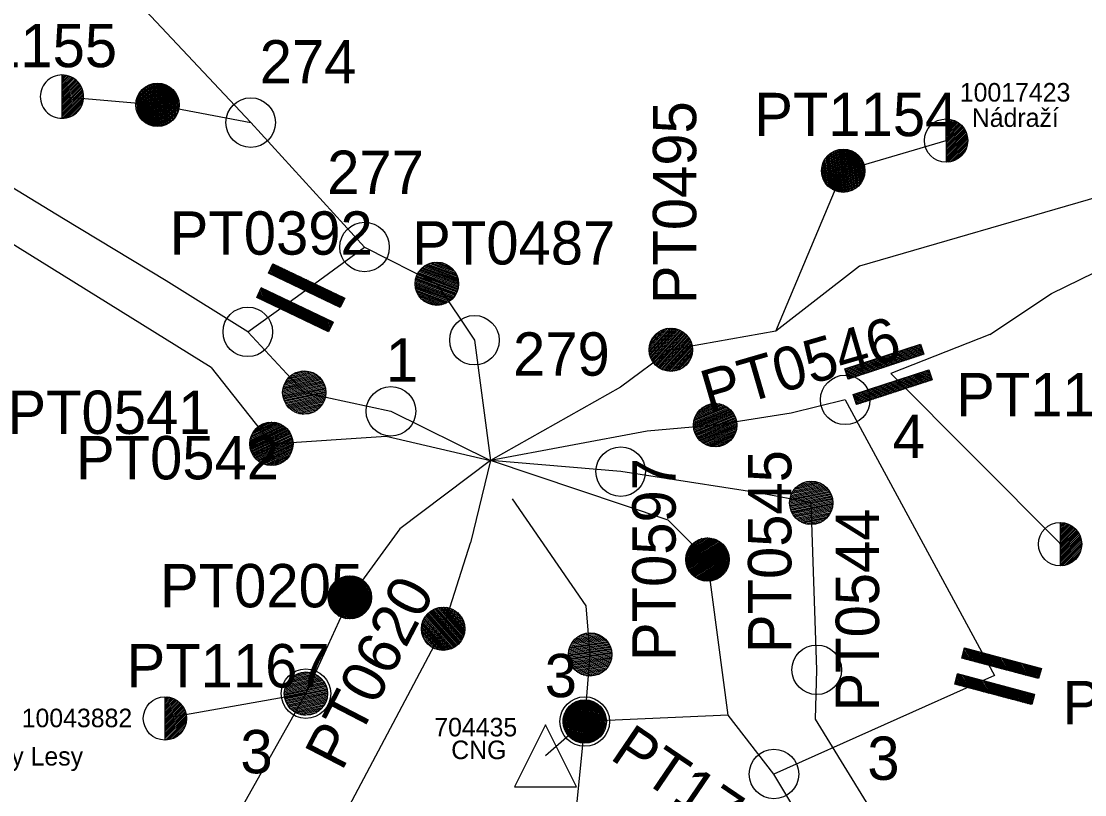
# Model space of a CAD drawing. Extents: x -788977 to -785292, y -1155262 to -1151579.
# Drawn here: x -787986 to -787127, y -1153978 to -1153353 of the extents above; entities that cross this region are included whole.
import ezdxf

# ---------------------------------------------------------------- set-up
doc = ezdxf.new("R2010")
doc.units = 0
for name, color, linetype in [('Default', 7, 'Continuous'), ('Vrstva 1', 7, 'Continuous'), ('Vrstva 2', 7, 'Continuous'), ('Vrstva 3', 7, 'Continuous'), ('Vrstva 44', 7, 'Continuous'), ('Vrstva 5', 7, 'Continuous')]:
    doc.layers.add(name, color=color, linetype=linetype)

# ---------------------------------------------------------------- blocks, each defined once
blk = doc.blocks.new('PS110')
at = {"layer": 'Default'}
for p, q in [((-15.14, 21.77), (-7.64, 29.27)), ((-15.14, 23.18), (-9.06, 29.27)), ((-15.14, 24.6), (-10.47, 29.27)), ((-15.14, 26.01), (-11.89, 29.27)), ((-15.14, 27.42), (-13.3, 29.27)), ((-15.14, 28.84), (-14.72, 29.27)), ((-15.14, 20.35), (-6.58, 28.92)), ((-15.14, 18.94), (-6.58, 27.5)), ((-15.14, 17.53), (-6.58, 26.09)), ((-6.58, -34.96), (-6.58, 29.27)), ((6.59, 22.11), (13.74, 29.27)), ((6.59, 20.7), (15.15, 29.26)), ((6.59, 23.53), (12.32, 29.26)), ((6.59, 24.94), (10.91, 29.26)), ((6.59, 26.36), (9.5, 29.26)), ((6.59, 27.77), (8.08, 29.26)), ((6.59, 29.18), (6.67, 29.26)), ((6.59, 19.29), (15.15, 27.85)), ((6.59, 17.87), (15.15, 26.44)), ((-15.14, 16.11), (-6.58, 24.68)), ((-15.14, 14.7), (-6.58, 23.26)), ((-15.14, 13.28), (-6.58, 21.85)), ((-15.14, 11.87), (-6.58, 20.43)), ((-15.14, 10.45), (-6.58, 19.02)), ((-15.14, 9.04), (-6.58, 17.61)), ((6.59, 16.46), (15.15, 25.02)), ((6.59, 15.04), (15.15, 23.61)), ((6.59, 13.63), (15.15, 22.19)), ((6.59, 12.21), (15.15, 20.78)), ((6.59, 10.8), (15.15, 19.37)), ((6.59, 9.39), (15.15, 17.95)), ((-15.14, 7.63), (-6.58, 16.19)), ((-15.14, 6.21), (-6.58, 14.78)), ((-15.14, 4.8), (-6.58, 13.36)), ((-15.14, 3.38), (-6.58, 11.95)), ((-15.14, 1.97), (-6.58, 10.54)), ((-15.14, 0.56), (-6.58, 9.12)), ((6.59, 7.97), (15.15, 16.54)), ((6.59, 6.56), (15.15, 15.12)), ((6.59, 5.14), (15.15, 13.71)), ((6.59, 3.73), (15.15, 12.29)), ((6.59, 2.32), (15.15, 10.88)), ((6.59, 0.9), (15.15, 9.47)), ((-15.14, -0.86), (-6.58, 7.71)), ((-15.14, -2.27), (-6.58, 6.29)), ((-15.14, -3.69), (-6.58, 4.88)), ((-15.14, -5.1), (-6.57, 3.46)), ((-15.14, -6.51), (-6.57, 2.05)), ((-15.14, -7.93), (-6.57, 0.64)), ((6.59, -0.51), (15.15, 8.05)), ((6.59, -1.93), (15.15, 6.64)), ((6.59, -3.34), (15.15, 5.22)), ((6.59, -4.75), (15.15, 3.81)), ((6.59, -6.17), (15.15, 2.4)), ((6.59, -7.58), (15.15, 0.98)), ((-15.14, -9.34), (-6.57, -0.78)), ((-15.14, -10.76), (-6.57, -2.19)), ((-15.14, -12.17), (-6.57, -3.61)), ((-15.14, -13.59), (-6.57, -5.02)), ((-15.14, -15), (-6.57, -6.43)), ((-15.14, -16.41), (-6.57, -7.85)), ((6.59, -9), (15.15, -0.43)), ((6.59, -10.41), (15.15, -1.85)), ((6.59, -11.83), (15.15, -3.26)), ((6.59, -13.24), (15.15, -4.67)), ((6.59, -14.65), (15.15, -6.09)), ((6.59, -16.07), (15.15, -7.5)), ((-15.14, -17.83), (-6.57, -9.26)), ((-15.14, -19.24), (-6.57, -10.68)), ((-15.14, -20.66), (-6.57, -12.09)), ((-15.14, -22.07), (-6.57, -13.5)), ((-15.14, -23.48), (-6.57, -14.92)), ((-15.14, -24.9), (-6.57, -16.33)), ((6.59, -17.48), (15.15, -8.92)), ((6.59, -18.9), (15.15, -10.33)), ((6.59, -20.31), (15.15, -11.74)), ((6.59, -21.72), (15.16, -13.16)), ((6.59, -23.14), (15.16, -14.57)), ((6.59, -24.55), (15.16, -15.99)), ((-15.14, -26.31), (-6.57, -17.75)), ((-15.14, -27.73), (-6.57, -19.16)), ((-15.14, -29.14), (-6.57, -20.58)), ((-15.14, -30.56), (-6.57, -21.99)), ((-15.14, -31.97), (-6.57, -23.4)), ((-15.14, -33.38), (-6.57, -24.82)), ((6.59, -25.97), (15.16, -17.4)), ((6.59, -27.38), (15.16, -18.82)), ((6.59, -28.79), (15.16, -20.23)), ((6.59, -30.21), (15.16, -21.64)), ((6.59, -31.62), (15.16, -23.06)), ((6.59, -33.04), (15.16, -24.47)), ((-15.14, -34.8), (-6.57, -26.23)), ((-13.89, -34.96), (-6.57, -27.65)), ((-12.47, -34.96), (-6.57, -29.06)), ((-11.06, -34.96), (-6.57, -30.47)), ((-9.64, -34.96), (-6.57, -31.89)), ((-8.23, -34.96), (-6.57, -33.3)), ((6.59, -34.45), (15.16, -25.89)), ((7.5, -34.96), (15.16, -27.3)), ((8.91, -34.96), (15.16, -28.71)), ((10.32, -34.96), (15.16, -30.13)), ((11.74, -34.96), (15.16, -31.54)), ((13.15, -34.96), (15.16, -32.96)), ((-6.82, -34.96), (-6.57, -34.72)), ((14.57, -34.96), (15.16, -34.37))]:
    blk.add_line(p, q, dxfattribs=at)
for points in [[(-6.58, 29.27), (-6.57, -34.96), (-15.14, -34.96), (-15.14, 29.27)], [(15.15, 29.27), (15.16, -34.96), (6.59, -34.96), (6.59, 29.26)]]:
    blk.add_lwpolyline(points, close=True, dxfattribs=at)
blk = doc.blocks.new('PS140')
at = {"layer": 'Default'}
for p, q in [((-17.49, -0.01), (0.01, 17.49)), ((-17.43, -1.37), (1.37, 17.43)), ((-17.42, 1.47), (-1.47, 17.42)), ((-17.29, -2.63), (2.63, 17.29)), ((-17.21, 3.1), (-3.1, 17.21)), ((-17.06, -3.82), (3.82, 17.06)), ((-16.77, -4.95), (4.95, 16.77)), ((-16.77, 4.95), (-4.95, 16.77)), ((-16.42, -6.01), (6.01, 16.42)), ((-16.02, -7.02), (7.02, 16.02)), ((-15.93, 7.2), (-7.2, 15.93)), ((-15.56, -7.98), (7.98, 15.56)), ((-15.06, -8.89), (8.89, 15.06)), ((-14.51, -9.76), (9.76, 14.51)), ((-13.92, -10.58), (10.58, 13.92)), ((-13.75, 10.8), (-10.8, 13.75)), ((-13.29, -11.36), (11.36, 13.29)), ((-12.62, -12.11), (12.11, 12.62)), ((-11.91, -12.81), (12.81, 11.91)), ((-11.15, -13.47), (13.47, 11.15)), ((-10.36, -14.09), (14.09, 10.36)), ((-9.52, -14.67), (14.67, 9.52)), ((-8.64, -15.2), (15.2, 8.64)), ((-7.72, -15.69), (15.69, 7.72)), ((-6.74, -16.13), (16.13, 6.74)), ((-5.72, -16.52), (16.52, 5.72)), ((-4.64, -16.86), (16.86, 4.64)), ((-3.5, -17.13), (17.13, 3.5)), ((-2.29, -17.34), (17.34, 2.29)), ((-1, -17.46), (17.46, 1)), ((0.39, -17.48), (17.48, -0.39)), ((1.91, -17.38), (17.38, -1.91)), ((3.59, -17.11), (17.11, -3.59)), ((5.53, -16.59), (16.59, -5.53)), ((7.96, -15.57), (15.57, -7.96))]:
    blk.add_line(p, q, dxfattribs=at)
blk.add_circle((0, 0), 17.49, dxfattribs=at)
blk = doc.blocks.new('PS150')
at = {"layer": 'Default'}
for p, q in [((-15.07, 22.36), (-7.37, 30.07)), ((-15.07, 23.78), (-8.78, 30.07)), ((-15.07, 25.19), (-10.2, 30.07)), ((-15.07, 26.6), (-11.61, 30.07)), ((-15.07, 28.02), (-13.03, 30.07)), ((-15.07, 29.43), (-14.44, 30.07)), ((-15.07, 20.95), (-6.51, 29.51)), ((-15.07, 19.53), (-6.51, 28.1)), ((-15.07, 18.12), (-6.51, 26.69)), ((6.66, 22.61), (14.12, 30.07)), ((6.66, 24.02), (12.7, 30.06)), ((6.66, 25.43), (11.29, 30.06)), ((6.66, 26.85), (9.87, 30.06)), ((6.66, 28.26), (8.46, 30.06)), ((6.66, 29.68), (7.04, 30.06)), ((6.66, 21.19), (15.22, 29.76)), ((6.66, 19.78), (15.22, 28.34)), ((6.66, 18.36), (15.22, 26.93)), ((-15.07, 16.71), (-6.51, 25.27)), ((-15.07, 15.29), (-6.51, 23.86)), ((-15.07, 13.88), (-6.51, 22.44)), ((-15.07, 12.46), (-6.51, 21.03)), ((-15.07, 11.05), (-6.51, 19.61)), ((-15.07, 9.64), (-6.51, 18.2)), ((6.66, 16.95), (15.22, 25.51)), ((6.66, 15.54), (15.22, 24.1)), ((6.66, 14.12), (15.22, 22.69)), ((6.66, 12.71), (15.22, 21.27)), ((6.66, 11.29), (15.22, 19.86)), ((6.66, 9.88), (15.22, 18.44)), ((-15.07, 8.22), (-6.51, 16.79)), ((-15.07, 6.81), (-6.51, 15.37)), ((-15.07, 5.39), (-6.51, 13.96)), ((-15.07, 3.98), (-6.5, 12.54)), ((-15.07, 2.56), (-6.5, 11.13)), ((-15.07, 1.15), (-6.5, 9.72)), ((6.66, 8.46), (15.22, 17.03)), ((6.66, 7.05), (15.22, 15.62)), ((6.66, 5.64), (15.22, 14.2)), ((6.66, 4.22), (15.22, 12.79)), ((6.66, 2.81), (15.22, 11.37)), ((6.66, 1.39), (15.22, 9.96)), ((-15.07, -0.26), (-6.5, 8.3)), ((-15.07, -1.68), (-6.5, 6.89)), ((-15.07, -3.09), (-6.5, 5.47)), ((-15.07, -4.51), (-6.5, 4.06)), ((-15.07, -5.92), (-6.5, 2.65)), ((-15.07, -7.33), (-6.5, 1.23)), ((6.66, -0.02), (15.22, 8.55)), ((6.66, -1.43), (15.22, 7.13)), ((6.66, -2.85), (15.22, 5.72)), ((6.66, -4.26), (15.22, 4.3)), ((6.66, -5.68), (15.22, 2.89)), ((6.66, -7.09), (15.22, 1.47)), ((6.66, -8.5), (15.22, 0.06)), ((-15.07, -8.75), (-6.5, -0.18)), ((-15.07, -10.16), (-6.5, -1.6)), ((-15.07, -11.58), (-6.5, -3.01)), ((-15.07, -12.99), (-6.5, -4.43)), ((-15.07, -14.4), (-6.5, -5.84)), ((-15.07, -15.82), (-6.5, -7.25)), ((6.66, -9.92), (15.22, -1.35)), ((6.66, -11.33), (15.22, -2.77)), ((6.66, -12.75), (15.22, -4.18)), ((6.66, -14.16), (15.23, -5.6)), ((6.66, -15.58), (15.23, -7.01)), ((6.66, -16.99), (15.23, -8.42)), ((-15.07, -17.23), (-6.5, -8.67)), ((-15.07, -18.65), (-6.5, -10.08)), ((-15.07, -20.06), (-6.5, -11.5)), ((-15.07, -21.48), (-6.5, -12.91)), ((-15.07, -22.89), (-6.5, -14.32)), ((-15.07, -24.3), (-6.5, -15.74)), ((-15.07, -25.72), (-6.5, -17.15)), ((6.66, -18.4), (15.23, -9.84)), ((6.66, -19.82), (15.23, -11.25)), ((6.66, -21.23), (15.23, -12.67)), ((6.66, -22.65), (15.23, -14.08)), ((6.66, -24.06), (15.23, -15.49)), ((6.66, -25.47), (15.23, -16.91)), ((-15.07, -27.13), (-6.5, -18.57)), ((-15.07, -28.55), (-6.5, -19.98)), ((-15.07, -29.96), (-6.5, -21.39)), ((-15.07, -31.37), (-6.5, -22.81)), ((-15.07, -32.79), (-6.5, -24.22)), ((-15.02, -34.16), (-6.5, -25.64)), ((6.66, -26.89), (15.23, -18.32)), ((6.66, -28.3), (15.23, -19.74)), ((6.66, -29.72), (15.23, -21.15)), ((6.66, -31.13), (15.23, -22.57)), ((6.66, -32.54), (15.23, -23.98)), ((6.66, -33.96), (15.23, -25.39)), ((-13.61, -34.16), (-6.5, -27.05)), ((-12.2, -34.16), (-6.5, -28.47)), ((-10.78, -34.16), (-6.5, -29.88)), ((-9.37, -34.16), (-6.5, -31.29)), ((-7.95, -34.16), (-6.5, -32.71)), ((-6.54, -34.16), (-6.5, -34.12)), ((7.87, -34.16), (15.23, -26.81)), ((9.29, -34.16), (15.23, -28.22)), ((10.7, -34.16), (15.23, -29.64)), ((12.12, -34.16), (15.23, -31.05)), ((13.53, -34.16), (15.23, -32.46)), ((14.95, -34.16), (15.23, -33.88))]:
    blk.add_line(p, q, dxfattribs=at)
for points in [[(-6.51, 30.07), (-6.5, -34.16), (-15.07, -34.16), (-15.07, 30.07)], [(15.22, 30.07), (15.23, -34.16), (6.66, -34.16), (6.66, 30.06)]]:
    blk.add_lwpolyline(points, close=True, dxfattribs=at)
blk = doc.blocks.new('PS610')
at = {"layer": 'Default'}
for p, q in [((0, 16.16), (1.27, 17.43)), ((0, 14.75), (2.54, 17.29)), ((0, 13.33), (3.75, 17.09)), ((0, 11.92), (4.86, 16.79)), ((0, 10.51), (5.93, 16.44)), ((0, 9.09), (6.95, 16.05)), ((0, 7.68), (7.9, 15.58)), ((0, 6.26), (8.83, 15.1)), ((0, 4.85), (9.69, 14.54)), ((0, 3.44), (10.52, 13.96)), ((0, 2.02), (11.3, 13.33)), ((0, 0.61), (12.05, 12.66)), ((0, -0.81), (12.76, 11.95)), ((0, -2.22), (13.42, 11.2)), ((0, -3.64), (14.05, 10.41)), ((0, -5.05), (14.62, 9.57)), ((0, -6.46), (15.17, 8.71)), ((0, -7.88), (15.65, 7.77)), ((0, -9.29), (16.1, 6.81)), ((0, -10.71), (16.49, 5.79)), ((0, -12.12), (16.83, 4.71)), ((0, -13.53), (17.12, 3.59)), ((0, -14.95), (17.32, 2.37)), ((0, -16.36), (17.44, 1.08)), ((0.29, -17.49), (17.48, -0.29)), ((1.78, -17.41), (17.4, -1.79)), ((3.46, -17.15), (17.14, -3.46)), ((5.36, -16.66), (16.65, -5.37)), ((7.78, -15.65), (15.64, -7.79))]:
    blk.add_line(p, q, dxfattribs=at)
blk.add_lwpolyline([(0, 17.5), (0, -17.5)], dxfattribs=at)
blk.add_circle((0, 0), 17.5, dxfattribs=at)
blk = doc.blocks.new('PS800')
at = {"layer": 'Vrstva 2'}
blk.add_circle((0, -0.01), 20, dxfattribs=at)
blk = doc.blocks.new('PS680')
at = {"layer": 'Vrstva 44'}
for points in [[(0, 25), (-25, -25)], [(25, -25), (0, 25)], [(-25, -25), (25, -25)]]:
    blk.add_lwpolyline(points, dxfattribs=at)
blk = doc.blocks.new('PS611')
at = {"layer": 'Default'}
for p, q in [((0, 16.16), (1.27, 17.43)), ((0, 14.75), (2.54, 17.29)), ((0, 13.33), (3.75, 17.09)), ((0, 11.92), (4.86, 16.79)), ((0, 10.51), (5.93, 16.44)), ((0, 9.09), (6.95, 16.05)), ((0, 7.68), (7.9, 15.58)), ((0, 6.26), (8.83, 15.1)), ((0, 4.85), (9.69, 14.54)), ((0, 3.44), (10.52, 13.96)), ((0, 2.02), (11.3, 13.33)), ((0, 0.61), (12.05, 12.66)), ((0, -0.81), (12.76, 11.95)), ((0, -2.22), (13.42, 11.2)), ((0, -3.64), (14.05, 10.41)), ((0, -5.05), (14.62, 9.57)), ((0, -6.46), (15.17, 8.71)), ((0, -7.88), (15.65, 7.77)), ((0, -9.29), (16.1, 6.81)), ((0, -10.71), (16.49, 5.79)), ((0, -12.12), (16.83, 4.71)), ((0, -13.53), (17.12, 3.59)), ((0, -14.95), (17.32, 2.37)), ((0, -16.36), (17.44, 1.08)), ((0.29, -17.49), (17.48, -0.29)), ((1.78, -17.41), (17.4, -1.79)), ((3.46, -17.15), (17.14, -3.46)), ((5.36, -16.66), (16.65, -5.37)), ((7.78, -15.65), (15.64, -7.79))]:
    blk.add_line(p, q, dxfattribs=at)
for points in [[(17.5, 0), (17.4, 1.83), (17.12, 3.64), (16.64, 5.4), (15.98, 7.11), (15.15, 8.75), (14.15, 10.28), (13, 11.71), (11.71, 13), (10.28, 14.15), (8.75, 15.15), (7.11, 15.98), (5.4, 16.64), (3.64, 17.12), (1.83, 17.4), (0, 17.5), (-1.83, 17.4), (-3.64, 17.12), (-5.41, 16.64), (-7.12, 15.98), (-8.75, 15.15), (-10.29, 14.15), (-11.71, 13), (-13.01, 11.71), (-14.16, 10.28), (-15.16, 8.75), (-15.99, 7.11), (-16.65, 5.4), (-17.12, 3.64), (-17.41, 1.83), (-17.5, 0), (-17.41, -1.83), (-17.12, -3.64), (-16.65, -5.41), (-15.99, -7.12), (-15.16, -8.75), (-14.16, -10.29), (-13.01, -11.71), (-11.71, -13.01), (-10.29, -14.16), (-8.75, -15.16), (-7.12, -15.99), (-5.41, -16.65), (-3.64, -17.12), (-1.83, -17.41), (0, -17.5), (1.83, -17.41), (3.64, -17.12), (5.4, -16.65), (7.12, -15.99), (8.75, -15.16), (10.28, -14.16), (11.71, -13.01), (13, -11.71), (14.15, -10.29), (15.15, -8.75), (15.98, -7.12), (16.64, -5.41), (17.12, -3.64), (17.4, -1.83), (17.5, 0)], [(0, 17.5), (0, -17.5)]]:
    blk.add_lwpolyline(points, dxfattribs=at)

msp = doc.modelspace()

# ---------------------------------------------------------------- linework, layer by layer
at = {"layer": 'Vrstva 1'}
for points in [[(-787800.3, -1153435.32), (-788178.23, -1153033.13)], [(-787802.65, -1153604.35), (-787868.47, -1153563.25), (-787951.48, -1153513.05), (-788037.33, -1153460.82), (-788120.57, -1153410.23), (-788202.39, -1153360.67), (-788288.25, -1153308.47), (-788374.07, -1153256.5), (-788458.44, -1153205.03)], [(-787832.21, -1153633.28), (-788475.59, -1153232.97)], [(-787952.67, -1153414.37), (-787875.54, -1153421.02)], [(-787875.54, -1153421.02), (-787800.3, -1153435.32), (-787800.3, -1153435.32)], [(-787708.42, -1153535.86), (-787800.3, -1153435.32)], [(-787321.97, -1153474.18), (-787239, -1153449.85)], [(-787376.49, -1153603.72), (-787321.97, -1153474.18)], [(-787115.82, -1153495.23), (-787308.8, -1153551.37)], [(-787153.82, -1153573.38), (-787083.9, -1153539.18), (-787008.76, -1153502.68), (-787008.76, -1153502.68)], [(-787762.51, -1153575.6), (-787708.42, -1153535.86)], [(-787708.42, -1153535.86), (-787650.11, -1153565.45)], [(-787308.8, -1153551.37), (-787376.49, -1153603.72)], [(-787650.11, -1153565.45), (-787619.68, -1153611.11)], [(-787802.65, -1153604.35), (-787762.51, -1153575.6)], [(-787203.57, -1153606.39), (-787153.82, -1153573.38)], [(-787802.65, -1153604.35), (-787757.05, -1153653.39)], [(-787619.68, -1153611.11), (-787606.65, -1153708.18)], [(-787376.49, -1153603.72), (-787461.19, -1153618.81)], [(-787203.57, -1153606.39), (-787283.58, -1153637.98)], [(-787461.19, -1153618.81), (-787501.91, -1153648.94)], [(-787832.21, -1153633.28), (-787783.64, -1153694.81)], [(-787283.58, -1153637.98), (-787147.54, -1153774.49), (-787146.93, -1153775.8)], [(-787757.05, -1153653.39), (-787687.11, -1153668.49)], [(-787501.91, -1153648.94), (-787606.65, -1153708.18)], [(-787320.4, -1153659.31), (-787363.89, -1153669.98)], [(-787320.4, -1153659.31), (-787199.75, -1153881.86)], [(-787687.11, -1153668.49), (-787606.65, -1153708.18)], [(-787363.89, -1153669.98), (-787425.41, -1153679.69)], [(-787425.41, -1153679.69), (-787480.21, -1153684.57)], [(-787783.64, -1153694.81), (-787690.84, -1153688.68)], [(-787690.84, -1153688.68), (-787606.65, -1153708.18)], [(-787480.21, -1153684.57), (-787606.65, -1153708.18)], [(-787606.65, -1153708.18), (-787679.88, -1153763.35)], [(-787606.65, -1153708.18), (-787622.94, -1153774.72)], [(-787463.21, -1153756.41), (-787606.65, -1153708.18)], [(-787501.64, -1153717.24), (-787606.65, -1153708.18)], [(-787347.79, -1153742.42), (-787390.67, -1153734.44), (-787501.64, -1153717.24)], [(-787529.43, -1153825.57), (-787588.93, -1153739.19)], [(-787343.38, -1153877.3), (-787347.79, -1153742.42)], [(-787431.55, -1153788.31), (-787463.21, -1153756.41)], [(-787679.88, -1153763.35), (-787720.21, -1153818.79)], [(-787644.99, -1153844.16), (-787622.94, -1153774.72)], [(-787414.8, -1153914.04), (-787431.55, -1153788.31)], [(-787720.21, -1153818.79), (-787755.7, -1153896.58)], [(-787526.29, -1153864.92), (-787529.43, -1153825.57)], [(-787784.52, -1154107.93), (-787644.99, -1153844.16)], [(-787530.66, -1153919.1), (-787526.29, -1153864.92)], [(-787344.28, -1153917.25), (-787343.38, -1153877.3)], [(-787199.75, -1153881.86), (-787377.92, -1153961.53)], [(-787755.7, -1153896.58), (-788440.76, -1155112.99)], [(-787755.7, -1153896.58), (-787869.52, -1153916.56)], [(-787530.66, -1153919.1), (-787562.24, -1153946.79)], [(-787530.66, -1153919.1), (-787542.46, -1154037.84)], [(-787414.8, -1153914.04), (-787530.66, -1153919.1)], [(-787377.92, -1153961.53), (-787414.8, -1153914.04)], [(-787293.67, -1153999.52), (-787344.28, -1153917.25), (-787344.28, -1153917.25)], [(-787337.78, -1154029.03), (-787377.92, -1153961.53)]]:
    msp.add_lwpolyline(points, dxfattribs=at)

# ---------------------------------------------------------------- block references
at = {"layer": 'Vrstva 2'}
for name, p, rotation in [('PS140', (-787875.54, -1153421.02), 49.98448057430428), ('PS140', (-787321.98, -1153474.18), 52.64485559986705), ('PS140', (-787650.11, -1153565.45), -65.3858777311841), ('PS110', (-787762.51, -1153575.6), 64.41102770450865), ('PS140', (-787461.19, -1153618.81), 2.7552722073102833), ('PS150', (-787283.58, -1153637.98), -71.80905273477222), ('PS140', (-787757.05, -1153653.39), -33.16308880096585), ('PS140', (-787425.41, -1153679.69), 157.24232784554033), ('PS140', (-787783.64, -1153694.81), 160.13660552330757), ('PS140', (-787347.79, -1153742.42), -33.688449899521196), ('PS140', (-787431.55, -1153788.31), 167.08118615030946), ('PS140', (-787720.21, -1153818.79), 85.84858058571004), ('PS140', (-787644.99, -1153844.16), -93.48196107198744), ('PS140', (-787526.29, -1153864.92), -36.519399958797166), ('PS110', (-787199.75, -1153881.86), 75.12431669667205), ('PS140', (-787755.7, -1153896.58), -32.98012495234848), ('PS140', (-787530.66, -1153919.1), 44.048112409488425)]:
    msp.add_blockref(name, p, dxfattribs=dict(at, rotation=rotation))
at = {"layer": 'Vrstva 3'}
for name, p in [('PS611', (-787952.67, -1153414.37)), ('PS610', (-787869.52, -1153916.56)), ('PS680', (-787562.24, -1153946.79))]:
    msp.add_blockref(name, p, dxfattribs=at)
for p, rotation in [((-787239, -1153449.86), 0.1407360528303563), ((-787146.93, -1153775.8), 0.011472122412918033)]:
    msp.add_blockref('PS610', p, dxfattribs=dict(at, rotation=rotation))
at = {"layer": 'Vrstva 5'}
for p, rotation in [((-787800.3, -1153435.32), -52.61854725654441), ((-787708.42, -1153535.86), -65.38587779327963), ((-787802.65, -1153604.35), -29.90867503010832), ((-787619.68, -1153611.11), 19.531444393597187), ((-787320.4, -1153659.31), 28.504486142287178), ((-787687.11, -1153668.49), -33.163088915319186), ((-787501.63, -1153717.24), -28.50299992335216), ((-787501.63, -1153717.24), -23.429574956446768), ((-787501.64, -1153717.24), -21.93631953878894), ((-787343.38, -1153877.3), -28.502902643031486), ((-787755.71, -1153896.58), -116.07586381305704), ((-787530.66, -1153919.1), -32.7110249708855), ((-787377.92, -1153961.53), 32.47125839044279)]:
    msp.add_blockref('PS800', p, dxfattribs=dict(at, rotation=rotation))

# ---------------------------------------------------------------- texts
at = {"layer": 'Vrstva 2'}
for s, p in [('PT1155', (-788072.11, -1153390.58)), ('PT1154', (-787393.78, -1153446.29)), ('PT0392', (-787865.72, -1153542.02)), ('PT0487', (-787669.93, -1153549.96)), ('PT1152', (-787230.78, -1153672.59)), ('PT0541', (-787996.71, -1153686.8)), ('PT0542', (-787941.35, -1153723.5)), ('PT0205', (-787873.52, -1153826.84)), ('PT1167', (-787900.51, -1153891.53)), ('PT0593', (-787144.96, -1153921.33))]:
    msp.add_text(s, height=35, dxfattribs=at).set_placement(p)
for s, rotation, p in [('PT0495', 90, (-787440.66, -1153582)), ('PT0546', 16.24, (-787430.45, -1153670.76)), ('PT0545', 90, (-787363.86, -1153863.79)), ('PT0597', 90, (-787457.26, -1153870.2)), ('PT0544', 90, (-787293.07, -1153910.97)), ('PT0620', 62.582, (-787726.78, -1153959.88)), ('PT1760', 325.831, (-787511.33, -1153948.77))]:
    msp.add_text(s, height=35, rotation=rotation, dxfattribs=at).set_placement(p)
at = {"layer": 'Vrstva 3'}
for s, p in [('10017423', (-787227.88, -1153418.36)), ('Nádraží', (-787218.19, -1153438.82)), ('10043882', (-787985.21, -1153923.72)), ('704435', (-787652.12, -1153931.12)), ('CNG', (-787638.47, -1153949.48)), ('Dílny Lesy', (-788029.29, -1153954.64))]:
    msp.add_text(s, height=15, dxfattribs=at).set_placement(p)
at = {"layer": 'Vrstva 5'}
for s, p in [('274', (-787793.08, -1153403.73)), ('277', (-787738.58, -1153492.94)), ('1', (-787691.17, -1153644.65)), ('279', (-787588.55, -1153639.74)), ('4', (-787282.08, -1153706.35)), ('3', (-787562.97, -1153899.44)), ('3', (-787808.66, -1153960.93)), ('3', (-787302.55, -1153966.24))]:
    msp.add_text(s, height=35, dxfattribs=at).set_placement(p)

doc.saveas('drawing.dxf')
